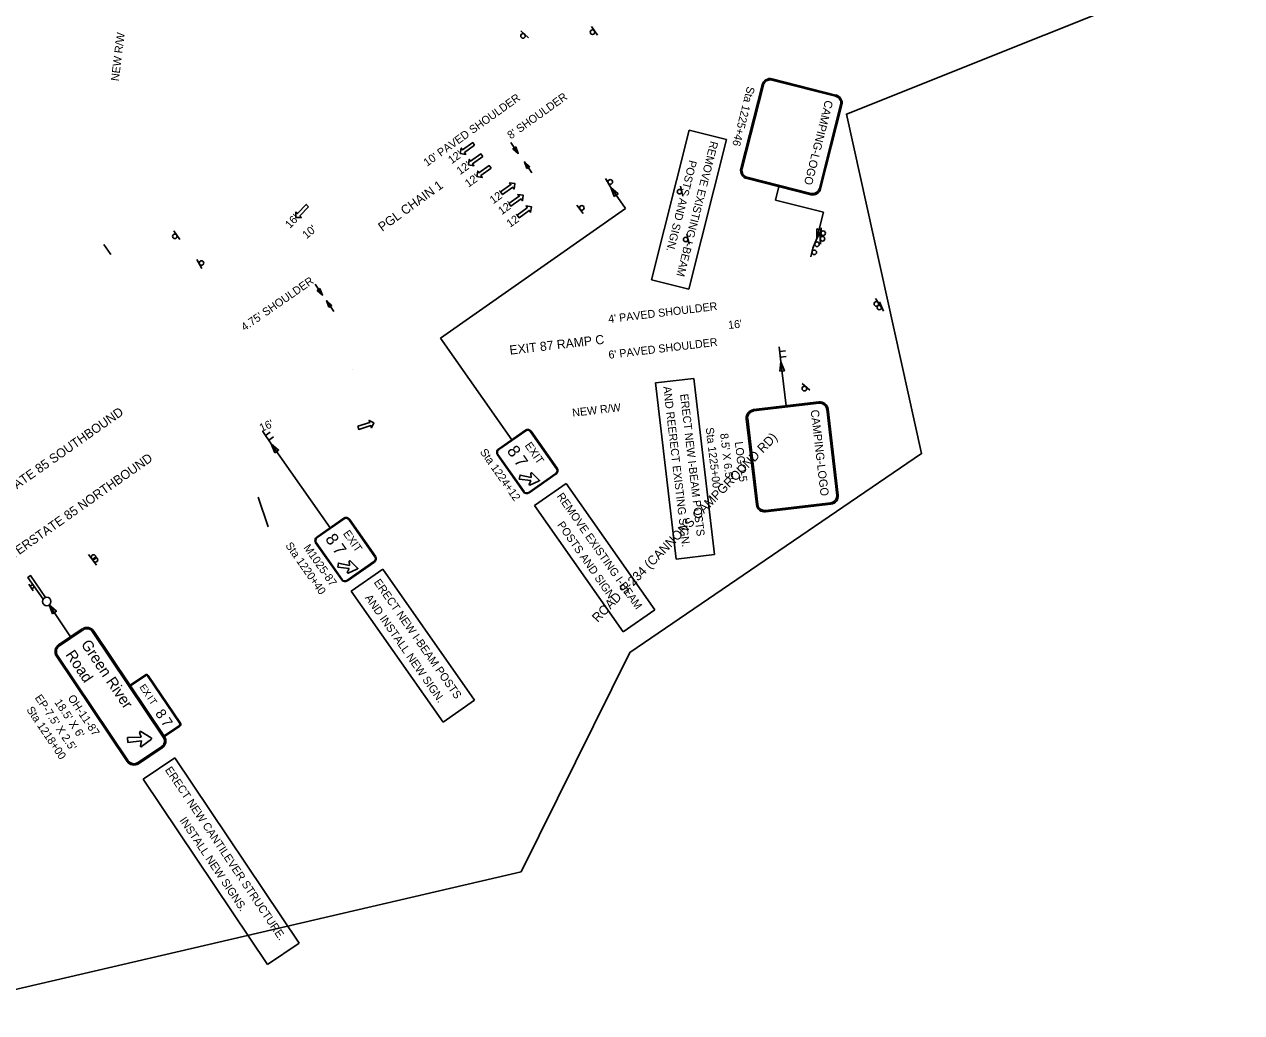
# Model space of a CAD drawing. Extents: x 1770940 to 1772558, y 1178099 to 1179642.
# Drawn here: x 1771494 to 1772558, y 1178099 to 1178963 of the extents above; entities that cross this region are included whole.
import ezdxf

# ---------------------------------------------------------------- set-up
doc = ezdxf.new("R2010")
doc.units = 0
for name, color, linetype in [('RD_PD_Final_LnLine', 7, 'Continuous'), ('RD_PD_Final_TX', 7, 'Continuous'), ('RD_PD_RW_TX', 7, 'Continuous'), ('RD_SHT_ShtClip', 7, 'Continuous'), ('RD_TX_Drainage', 7, 'Continuous'), ('RD_TX_RoadID', 7, 'Continuous'), ('SN_P_Signs', 7, 'Continuous')]:
    doc.layers.add(name, color=color, linetype=linetype)

# ---------------------------------------------------------------- blocks, each defined once
blk = doc.blocks.new('SARRW2')
at = {"layer": 'RD_PD_Final_LnLine'}
blk.add_lwpolyline([(-12, 1.2), (-12, -1.2), (-2.83, -1.2), (-2.83, -2.83), (0, 0), (-2.83, 2.83), (-2.83, 1.2)], close=True, dxfattribs=at)
blk = doc.blocks.new('AH')
at = {"layer": 'RD_TX_Drainage'}
blk.add_lwpolyline([(-6, 1.5), (0, 0), (-6, -1.5)], close=True, dxfattribs=at)

msp = doc.modelspace()

# ---------------------------------------------------------------- linework, layer by layer
at = {"layer": 'RD_PD_Final_TX'}
for p, q in [((1771925.5, 1178850.6), (1771918.9, 1178860)), ((1771930.8, 1178843.1), (1771937.3, 1178833.6)), ((1771754.3, 1178726.7), (1771747.8, 1178736.1)), ((1771757.8, 1178721.8), (1771764.3, 1178712.3))]:
    msp.add_line(p, q, dxfattribs=at)
at = {"layer": 'RD_SHT_ShtClip'}
msp.add_lwpolyline([(1771296.2, 1178245.5), (1771109.1, 1178512.4), (1770940, 1178753.7), (1771317.8, 1179011.2), (1771643.5, 1178998.1), (1772001.7, 1179411.7), (1772162.5, 1179241.9), (1772385.8, 1179331.3), (1772558.1, 1179023.3), (1772212.5, 1178884.9), (1772278.1, 1178588), (1772022.9, 1178414.1), (1771928, 1178222.3), (1771398.9, 1178099.1)], close=True, dxfattribs=at)
at = {"layer": 'SN_P_Signs'}
for p, q in [((1771934.3, 1178951.6), (1771927.8, 1178957.9)), ((1771994.7, 1178954.1), (1771989.6, 1178961.4)), ((1772041.9, 1178740.1), (1772075, 1178871)), ((1772075, 1178871), (1772107.6, 1178862.7)), ((1772107.6, 1178862.7), (1772074.5, 1178731.8)), ((1772001.9, 1178828.6), (1772006.4, 1178820.7)), ((1772019.2, 1178802.4), (1772006.4, 1178820.7)), ((1772069.5, 1178813.1), (1772067.4, 1178821.9)), ((1772153.3, 1178821.5), (1772150.3, 1178809.8)), ((1772150.3, 1178809.8), (1772192.4, 1178799.1)), ((1772019.2, 1178802.4), (1771857.6, 1178689.1)), ((1771976.8, 1178805.3), (1771982.2, 1178798.1)), ((1772192.4, 1178799.1), (1772186.6, 1178776)), ((1772190.3, 1178785.4), (1772189.8, 1178776.4)), ((1771629.4, 1178775.4), (1771624.3, 1178782.8)), ((1772074.8, 1178771.3), (1772072.9, 1178780.1)), ((1772186.6, 1178776), (1772183, 1178767.8)), ((1772189.1, 1178780.2), (1772189.9, 1178771.2)), ((1771569.1, 1178762.1), (1771563.2, 1178770.9)), ((1772183.5, 1178768.9), (1772181.2, 1178760.2)), ((1771644.5, 1178757.7), (1771648.9, 1178749.8)), ((1772074.5, 1178731.8), (1772041.9, 1178740.1)), ((1772242.7, 1178716.2), (1772237.8, 1178723.7)), ((1772244.9, 1178712.5), (1772241.3, 1178720.7)), ((1771919.9, 1178600.2), (1771857.6, 1178689.1)), ((1772155.2, 1178668.4), (1772153.7, 1178681.3)), ((1772154.2, 1178677.3), (1772159.1, 1178677.8)), ((1772154.8, 1178672.3), (1772159.7, 1178672.9)), ((1772159.8, 1178629.8), (1772155.2, 1178668.4)), ((1771780.8, 1178661.5), (1771780.8, 1178661.5)), ((1772045.5, 1178649.8), (1772078.9, 1178653.7)), ((1772063.7, 1178495.8), (1772045.5, 1178649.8)), ((1772078.9, 1178653.7), (1772097, 1178499.7)), ((1772180.5, 1178643.6), (1772173.6, 1178649.3)), ((1771709.5, 1178596.6), (1771702.1, 1178607.3)), ((1771704.4, 1178603.9), (1771708.5, 1178606.8)), ((1771908.1, 1178591.9), (1771931.7, 1178608.5)), ((1771908.5, 1178591.5), (1771932, 1178608)), ((1771936.2, 1178607.2), (1771958.9, 1178574.8)), ((1771936.7, 1178607.6), (1771959.4, 1178575.2)), ((1771707.3, 1178599.8), (1771711.4, 1178602.7)), ((1771761, 1178523.2), (1771709.5, 1178596.6)), ((1771930, 1178554.5), (1771907.2, 1178586.9)), ((1771930.5, 1178554.8), (1771907.7, 1178587.3)), ((1771958.2, 1178570.6), (1771934.6, 1178554.1)), ((1771958.6, 1178570.2), (1771935, 1178553.6)), ((1771939.7, 1178542.6), (1771967.3, 1178561.9)), ((1771967.3, 1178561.9), (1772044.8, 1178451.4)), ((1771706.7, 1178524.1), (1771697.9, 1178550)), ((1772017.3, 1178432.1), (1771939.7, 1178542.6)), ((1771749.2, 1178514.9), (1771772.8, 1178531.5)), ((1771749.6, 1178514.5), (1771773.2, 1178531)), ((1771777.3, 1178530.3), (1771800.1, 1178497.8)), ((1771777.8, 1178530.6), (1771800.6, 1178498.2)), ((1771771.1, 1178477.5), (1771748.3, 1178509.9)), ((1771771.6, 1178477.8), (1771748.8, 1178510.3)), ((1771549.8, 1178499.9), (1771555.1, 1178492.6)), ((1772097, 1178499.7), (1772063.7, 1178495.8)), ((1771551.4, 1178497.7), (1771556.7, 1178490.4)), ((1771799.3, 1178493.6), (1771775.7, 1178477.1)), ((1771799.7, 1178493.2), (1771776.1, 1178476.6)), ((1771779.4, 1178467.7), (1771807, 1178487)), ((1771807, 1178487), (1771887.3, 1178372.3)), ((1771501.4, 1178468.1), (1771497.4, 1178473.8)), ((1771500.9, 1178473.6), (1771498.6, 1178472)), ((1771502.4, 1178471.4), (1771500.2, 1178469.8)), ((1771859.8, 1178353), (1771779.4, 1178467.7)), ((1771533.9, 1178427.8), (1771515.2, 1178455.7)), ((1772044.8, 1178451.4), (1772017.3, 1178432.1)), ((1771523.5, 1178420.9), (1771544.2, 1178434.8)), ((1771524.2, 1178419.9), (1771544.9, 1178433.8)), ((1771887.3, 1178372.3), (1771859.8, 1178353)), ((1771613.5, 1178331.7), (1771592.8, 1178317.8)), ((1771614.1, 1178330.7), (1771593.4, 1178316.8)), ((1771597.4, 1178303.2), (1771625.3, 1178321.9)), ((1771625.3, 1178321.9), (1771734, 1178160)), ((1771706.1, 1178141.3), (1771597.4, 1178303.2)), ((1771734, 1178160), (1771706.1, 1178141.3))]:
    msp.add_line(p, q, dxfattribs=at)
for points in [[(1772147.1, 1178914.6), (1772203, 1178900.5)], [(1772147.4, 1178915.8), (1772203.3, 1178901.6)], [(1772120.1, 1178837.3), (1772138.7, 1178910.6)], [(1772121.3, 1178837), (1772139.9, 1178910.3)], [(1772207.3, 1178893.2), (1772188.8, 1178819.9)], [(1772208.5, 1178892.9), (1772189.9, 1178819.6)], [(1772181.2, 1178814.4), (1772125.3, 1178828.5)], [(1772181.5, 1178815.6), (1772125.6, 1178829.7)], [(1772131.2, 1178626.5), (1772188.4, 1178633.2)], [(1772131.3, 1178625.3), (1772188.5, 1178632)], [(1772195.2, 1178626.8), (1772204, 1178551.7)], [(1772196.4, 1178626.9), (1772205.2, 1178551.8)], [(1772133.7, 1178543.4), (1772124.9, 1178618.5)], [(1772134.9, 1178543.5), (1772126.1, 1178618.6)], [(1771926.4, 1178565.8), (1771927.1, 1178569.3), (1771936.9, 1178567.2)], [(1771936.4, 1178564.5), (1771926.4, 1178565.8)], [(1771934.9, 1178561.1), (1771936.4, 1178564.5)], [(1771943.8, 1178564.2), (1771935.5, 1178560.5)], [(1771936.9, 1178567.2), (1771936.6, 1178570.8)], [(1771937.4, 1178571.2), (1771943.9, 1178564.9)], [(1772198.8, 1178545), (1772141.6, 1178538.3)], [(1772198.9, 1178543.8), (1772141.7, 1178537.1)], [(1771767.6, 1178488.8), (1771768.2, 1178492.3), (1771778, 1178490.2)], [(1771777.5, 1178487.5), (1771767.6, 1178488.8)], [(1771776, 1178484.1), (1771777.5, 1178487.5)], [(1771784.9, 1178487.2), (1771776.6, 1178483.5)], [(1771778, 1178490.2), (1771777.7, 1178493.8)], [(1771778.5, 1178494.2), (1771785, 1178487.9)], [(1771512.1, 1178462.3), (1771499, 1178481.4), (1771496.7, 1178479.8), (1771509.9, 1178460.6)], [(1771553.2, 1178432.1), (1771615.1, 1178340)], [(1771554.2, 1178432.8), (1771616.1, 1178340.7)], [(1771583.4, 1178318.8), (1771521.6, 1178410.9)], [(1771584.4, 1178319.4), (1771522.6, 1178411.5)], [(1771599.8, 1178394), (1771586.3, 1178385), (1771586, 1178385.5), (1771599.4, 1178394.5)], [(1771629.5, 1178351.9), (1771601.4, 1178393.7)], [(1771601.9, 1178394), (1771630, 1178352.2)], [(1771615.8, 1178341.2), (1771629.2, 1178350.2)], [(1771629.5, 1178349.7), (1771616.1, 1178340.7), (1771615.8, 1178341.2)], [(1771584.1, 1178335.4), (1771583.8, 1178339.6), (1771595.7, 1178339.9)], [(1771595.7, 1178339.9), (1771594.4, 1178344.2)], [(1771595.3, 1178344.9), (1771604.6, 1178339.4)], [(1771604.7, 1178338.4), (1771596.1, 1178331.8)], [(1771595.9, 1178336.7), (1771584.1, 1178335.4)], [(1771595.2, 1178332.3), (1771595.9, 1178336.7)]]:
    msp.add_lwpolyline(points, dxfattribs=at)
for points in [[(1772009.4, 1178812.8), (1772006.4, 1178820.7), (1772012.8, 1178815.2)], [(1772190.6, 1178783.5), (1772186.6, 1178776), (1772186.6, 1178784.5)], [(1772154.1, 1178660), (1772155.2, 1178668.4), (1772158.2, 1178660.5)], [(1771712.6, 1178588.7), (1771709.5, 1178596.6), (1771715.9, 1178591.1)], [(1771518.2, 1178447.8), (1771515.2, 1178455.7), (1771521.6, 1178450.1)]]:
    msp.add_lwpolyline(points, close=True, dxfattribs=at)
for centre, radius in [((1771990.4, 1178956.6), 2), ((1771929.6, 1178953.3), 2), ((1772005.9, 1178825.6), 2), ((1772066.5, 1178817.1), 2), ((1771981.1, 1178802.9), 2), ((1771625.2, 1178778), 2), ((1772071.9, 1178775.3), 2), ((1772191.5, 1178775.9), 2), ((1772192.1, 1178780.8), 2), ((1772184.3, 1178764), 2), ((1772186.7, 1178771.1), 2), ((1771648.5, 1178754.7), 2), ((1772238.6, 1178718.9), 2), ((1772241.2, 1178715.8), 2), ((1772175.7, 1178644.9), 2), ((1771554.1, 1178497.5), 2), ((1771555.7, 1178495.2), 2), ((1771513.1, 1178458.7), 3.71)]:
    msp.add_circle(centre, radius, dxfattribs=at)
for centre, radius, start, end in [((1772145.7, 1178908.8), 7.2, 75.7849, 165.7849), ((1772145.7, 1178908.8), 6, 75.7849, 165.7849), ((1772201.5, 1178894.7), 6, 345.7849, 75.7849), ((1772201.5, 1178894.7), 7.2, 345.7849, 75.7849), ((1772127.1, 1178835.5), 7.2, 165.7849, 255.7849), ((1772127.1, 1178835.5), 6, 165.7849, 255.7849), ((1772182.9, 1178821.4), 7.2, 255.7849, 345.7849), ((1772182.9, 1178821.4), 6, 255.7849, 345.7849), ((1772132, 1178619.3), 7.2, 96.7321, 186.7321), ((1772189.2, 1178626.1), 7.2, 6.7321, 96.7321), ((1772189.2, 1178626.1), 6, 6.7321, 96.7321), ((1772132, 1178619.3), 6, 96.7321, 186.7321), ((1771933.8, 1178605.5), 3.6, 35.0302, 125.0302), ((1771933.8, 1178605.5), 3, 35.0302, 125.0302), ((1771910.2, 1178589), 3.6, 125.0302, 215.0302), ((1771910.2, 1178589), 3, 125.0302, 215.0302), ((1771956.5, 1178573.1), 3, 305.0302, 35.0302), ((1771956.5, 1178573.1), 3.6, 305.0302, 35.0302), ((1771937.1, 1178570.9), 0.45, 46.2081, 183.9923), ((1771943.6, 1178564.6), 0.45, 293.8523, 46.2081), ((1771932.9, 1178556.6), 3.6, 215.0302, 305.0302), ((1771932.9, 1178556.6), 3, 215.0302, 305.0302), ((1771935.3, 1178561), 0.45, 156.0681, 293.8523), ((1772198.1, 1178551), 6, 276.7321, 6.7321), ((1772198.1, 1178551), 7.2, 276.7321, 6.7321), ((1772140.9, 1178544.2), 7.2, 186.7321, 276.7321), ((1772140.9, 1178544.2), 6, 186.7321, 276.7321), ((1771774.9, 1178528.5), 3.6, 35.0302, 125.0302), ((1771774.9, 1178528.5), 3, 35.0302, 125.0302), ((1771751.3, 1178512), 3.6, 125.0302, 215.0302), ((1771751.3, 1178512), 3, 125.0302, 215.0302), ((1771797.6, 1178496.1), 3, 305.0302, 35.0302), ((1771797.6, 1178496.1), 3.6, 305.0302, 35.0302), ((1771778.2, 1178493.9), 0.45, 46.2081, 183.9923), ((1771784.7, 1178487.6), 0.45, 293.8523, 46.2081), ((1771774, 1178479.6), 3.6, 215.0302, 305.0302), ((1771774, 1178479.6), 3, 215.0302, 305.0302), ((1771776.5, 1178484), 0.45, 156.0681, 293.8523), ((1771548.3, 1178428.8), 7.2, 33.8829, 123.8829), ((1771548.3, 1178428.8), 6, 33.8829, 123.8829), ((1771527.6, 1178414.9), 7.2, 123.8829, 213.8829), ((1771527.6, 1178414.9), 6, 123.8829, 213.8829), ((1771600.4, 1178393), 1.8, 33.8829, 123.8829), ((1771600.4, 1178393), 1.2, 33.8829, 123.8829), ((1771628.5, 1178351.2), 1.2, 303.8829, 33.8829), ((1771628.5, 1178351.2), 1.8, 303.8829, 33.8829), ((1771595, 1178344.4), 0.6, 59.8636, 197.329), ((1771604.3, 1178338.9), 0.6, 307.9023, 59.8636), ((1771610.1, 1178336.7), 6, 303.8829, 33.8829), ((1771610.1, 1178336.7), 7.2, 303.8829, 33.8829), ((1771595.8, 1178332.2), 0.6, 170.4368, 307.9023), ((1771589.4, 1178322.8), 7.2, 213.8829, 303.8829), ((1771589.4, 1178322.8), 6, 213.8829, 303.8829)]:
    msp.add_arc(centre, radius, start, end, dxfattribs=at)

# ---------------------------------------------------------------- block references
at = {"layer": 'RD_PD_Final_LnLine'}
for p, xscale, yscale, rotation in [((1771874.8, 1178850.5), 1.1999999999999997, 1.2000000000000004, -144.38650217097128), ((1771881.9, 1178840.6), 1.1999999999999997, 1.2000000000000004, -144.38650217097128), ((1771889.2, 1178830.4), 1.1999999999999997, 1.2000000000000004, -144.38650217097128), ((1771922.6, 1178824.1), 1.1999999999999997, 1.2, 35.61349782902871), ((1771731.1, 1178794.5), 1.1999999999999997, 1.2000000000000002, -133.8541065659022), ((1771929.9, 1178813.9), 1.1999999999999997, 1.2, 35.61349782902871), ((1771937, 1178803.9), 1.1999999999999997, 1.2, 35.61349782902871), ((1771799.3, 1178614.9), 1.2, 1.2000000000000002, 17.742172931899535)]:
    msp.add_blockref('SARRW2', p, dxfattribs=dict(at, xscale=xscale, yscale=yscale, rotation=rotation))
at = {"layer": 'RD_PD_Final_TX'}
for p, rotation in [((1771925.5, 1178850.6), -54.96983550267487), ((1771930.8, 1178843.1), 124.27931028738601), ((1771754.3, 1178726.7), -54.96983550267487), ((1771757.8, 1178721.8), 124.27931028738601)]:
    msp.add_blockref('AH', p, dxfattribs=dict(at, rotation=rotation))

# ---------------------------------------------------------------- texts
for s, rotation, p in [("10' PAVED SHOULDER", 35.6135, (1771845.7, 1178838.8)), ("8' SHOULDER", 35.6135, (1771919, 1178862.7)), ("12'", 35.6135, (1771867.2, 1178841)), ("12'", 35.6135, (1771874.6, 1178831.5)), ("12'", 35.6135, (1771881.9, 1178820.5)), ("12'", 35.6135, (1771903.6, 1178806)), ("12'", 35.6135, (1771911, 1178796.5)), ("16'", 46.1459, (1771725.8, 1178784.5)), ("12'", 35.6135, (1771918.3, 1178785.4)), ("10'", 39.8251, (1771740.3, 1178775.4)), ("4.75' SHOULDER", 34.8311, (1771686.1, 1178694.9)), ("4' PAVED SHOULDER", 6.8605, (1772004.6, 1178702.2)), ("16'", 5.6938, (1772109.3, 1178697)), ("6' PAVED SHOULDER", 6.8605, (1772004.8, 1178670.9)), ("16'", 23.2402, (1771700.9, 1178606.9))]:
    msp.add_text(s, height=7, rotation=rotation, dxfattribs=at).set_placement(p)
at = {"layer": 'RD_PD_RW_TX'}
for rotation, p in [(82.8056, (1771576.1, 1178913.5)), (6.7321, (1771973.1, 1178620.2))]:
    msp.add_text('NEW R/W', height=7, rotation=rotation, dxfattribs=at).set_placement(p)
at = {"layer": 'RD_TX_RoadID'}
for s, rotation, p in [('PGL CHAIN 1', 35.9432, (1771806.6, 1178781.9)), ('EXIT 87 RAMP C', 6.6324, (1771918.3, 1178674.5)), ('INTERSTATE 85 SOUTHBOUND', 35.0884, (1771449.7, 1178530.4)), ('ROAD S-234 (CANNONS CAMPGROUND RD)', 45.6964, (1771994.9, 1178439.9)), ('INTERSTATE 85 NORTHBOUND', 35.2829, (1771475, 1178489.3))]:
    msp.add_text(s, height=8, rotation=rotation, dxfattribs=at).set_placement(p)
at = {"layer": 'SN_P_Signs'}
for s, height, rotation, p in [('Sta 1225+46', 7, 255.785, (1772125.7, 1178909.6)), ('CAMPING-LOGO', 7.2, 255.7849, (1772193.9, 1178897.6)), ('REMOVE EXISTING I-BEAM', 7, 255.785, (1772093.6, 1178861.8)), ('POSTS AND SIGN.', 7, 255.785, (1772075, 1178845.2)), ('AND REERECT EXISTING SIGN.', 7, 276.7322, (1772052.2, 1178646.5)), ('ERECT NEW I-BEAM POSTS', 7, 276.7322, (1772067, 1178639.9)), ('CAMPING-LOGO', 7.2, 276.7321, (1772181.1, 1178626)), ('Sta 1225+00', 7, 276.7322, (1772089.4, 1178610.5)), ("8.5' X 6.5'", 7, 276.7322, (1772102, 1178605.4)), ('8', 10.8, 305.0302, (1771915.1, 1178590.4)), ('EXIT', 7, 305.0302, (1771930.8, 1178595.1)), ('LOGO-5', 7, 276.7322, (1772114.8, 1178598.1)), ('Sta 1224+12', 7, 305.0302, (1771891.6, 1178589.4)), ('7', 10.8, 305.0302, (1771921.3, 1178581.4)), ('REMOVE EXISTING I-BEAM', 7, 305.0302, (1771958.8, 1178550.7)), ('EXIT', 7, 305.0302, (1771771.9, 1178518.1)), ('POSTS AND SIGN.', 7, 305.0302, (1771959.2, 1178525.7)), ('Sta 1220+40', 7, 305.0302, (1771721.5, 1178507.6)), ('M1025-87', 7, 305.0302, (1771737.4, 1178505.7)), ('8', 10.8, 305.0302, (1771756.2, 1178513.4)), ('7', 10.8, 305.0302, (1771762.5, 1178504.4)), ('ERECT NEW I-BEAM POSTS', 7, 305.0302, (1771798.8, 1178475.4)), ('AND INSTALL NEW SIGN.', 7, 305.0302, (1771791.1, 1178461.9)), ('Green River', 9.6, 303.8829, (1771542.7, 1178421.3)), ('Road', 9.6, 303.8829, (1771529.2, 1178412.2)), ('E', 6, 303.8829, (1771593.9, 1178383.9)), ('X', 6, 303.8829, (1771596.8, 1178379.6)), ("EP-7.5' X 2.5'", 7, 303.883, (1771502.4, 1178374.5)), ("18.5' X 6'", 7, 303.883, (1771519.5, 1178370.5)), ('OH-11-87', 7, 303.883, (1771531.2, 1178374.3)), ('I', 6, 303.8829, (1771600.6, 1178374)), ('T', 6, 303.8829, (1771602.3, 1178371.5)), ('Sta 1218+00', 7, 303.883, (1771495.1, 1178364)), ('8', 9, 303.8829, (1771607.6, 1178360.8)), ('7', 9, 303.8829, (1771612.7, 1178353.3)), ('ERECT NEW CANTILEVER STRUCTURE.', 7, 303.883, (1771616.2, 1178311.4)), ('INSTALL NEW SIGNS.', 7, 303.883, (1771629, 1178267.3))]:
    msp.add_text(s, height=height, rotation=rotation, dxfattribs=at).set_placement(p)

doc.saveas('drawing.dxf')
